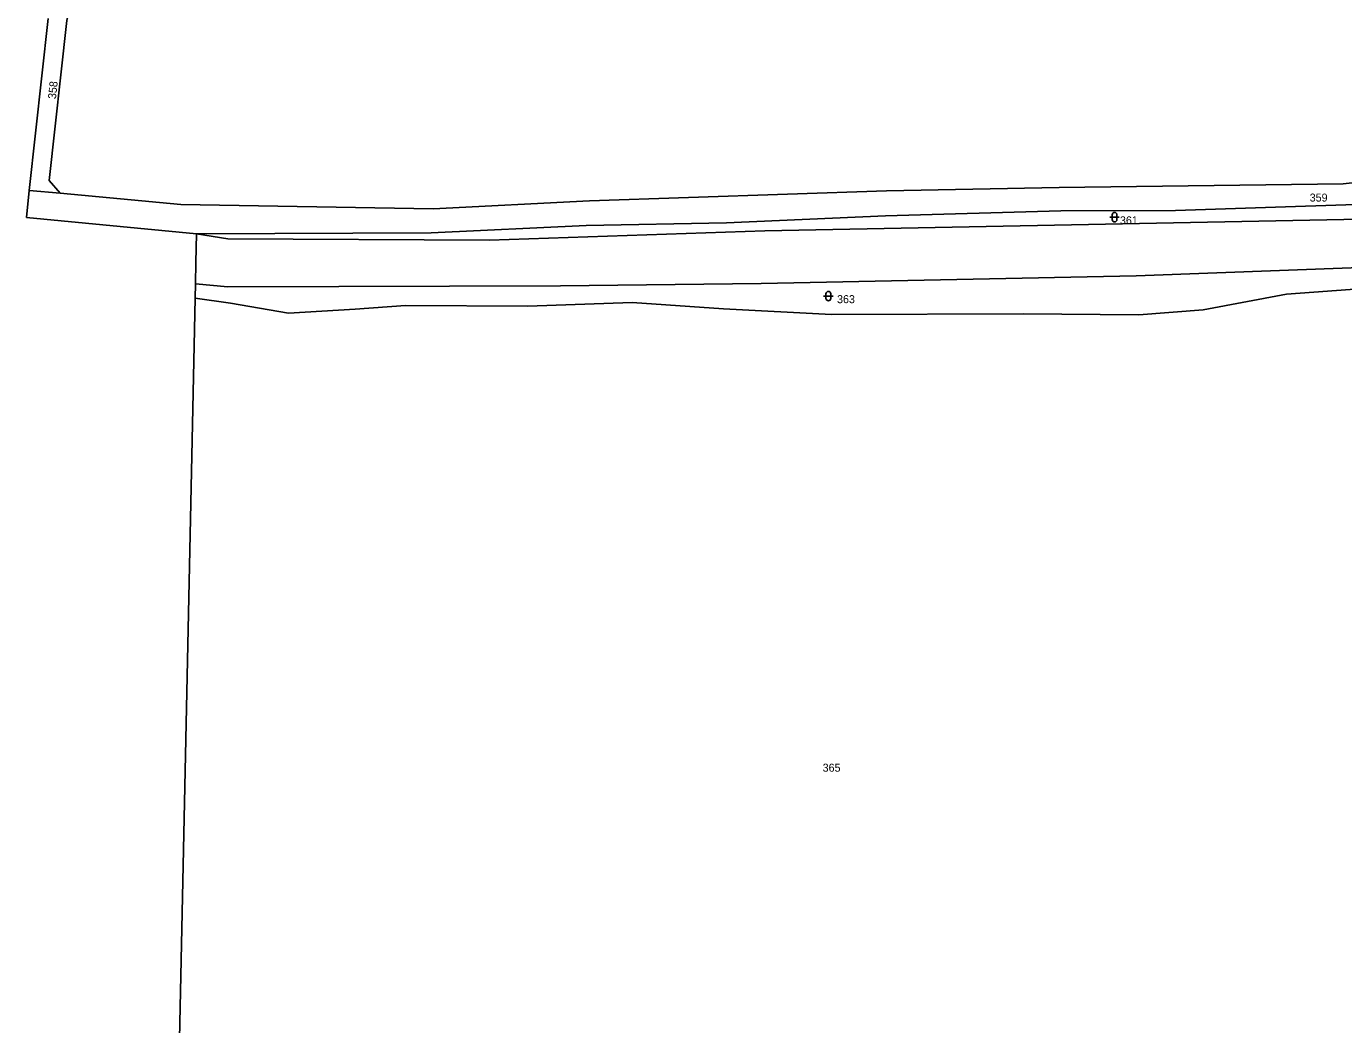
# Model space of a CAD drawing. Extents: x -769392 to -767038, y -1018329 to -1015269.
# Drawn here: x -769084.7 to -768805, y -1016297.6 to -1016085.5 of the extents above; entities that cross this region are included whole.
import ezdxf

# ---------------------------------------------------------------- set-up
doc = ezdxf.new("R2010")
doc.units = 0
doc.header["$LTSCALE"] = 0.68
doc.layers.add('1', color=7, linetype='Continuous', lineweight=25)
doc.layers.add('3', color=7, linetype='Continuous', lineweight=25)
doc.layers.add('2', color=7, linetype='Continuous')

msp = doc.modelspace()

# ---------------------------------------------------------------- linework, layer by layer
at = {"layer": '1'}
for p, q in [((-769080.14, -1016083.85), (-769084.11, -1016120.36)), ((-769084.11, -1016120.36), (-769084.74, -1016126.1)), ((-769084.11, -1016120.36), (-769077.57, -1016120.97)), ((-769084.74, -1016126.1), (-769048.63, -1016129.62)), ((-769048.85, -1016140.19), (-769048.91, -1016143.24)), ((-769048.91, -1016143.24), (-769052.49, -1016313.52))]:
    msp.add_line(p, q, dxfattribs=at)
for points in [[(-769072.33, -1016067.68), (-769076.16, -1016084.29), (-769079.86, -1016118.25), (-769077.57, -1016120.97)], [(-769077.57, -1016120.97), (-769051.96, -1016123.35), (-768998.31, -1016124.28), (-768965.15, -1016122.6), (-768902.06, -1016120.44), (-768865.37, -1016119.73), (-768805.12, -1016118.98), (-768769.94, -1016115), (-768749.97, -1016114.84), (-768736.74, -1016116.15), (-768689.9, -1016125.81), (-768656.93, -1016129.38), (-768637.88, -1016131.28), (-768596.9, -1016133.83)], [(-768594.7, -1016141.25), (-768631.63, -1016137.21), (-768650.19, -1016134.74), (-768717.39, -1016127.21), (-768738.73, -1016121.28), (-768749.98, -1016120.03), (-768769.94, -1016120.01), (-768778.71, -1016121.23), (-768783.28, -1016122.74), (-768840.7, -1016124.64), (-768865.08, -1016124.72), (-768902.28, -1016125.77), (-768936.05, -1016127.23), (-768965.85, -1016127.81), (-768998.75, -1016129.36), (-769048.63, -1016129.62)], [(-769048.63, -1016129.62), (-769041.93, -1016130.68), (-768986.37, -1016130.93), (-768927.89, -1016128.95), (-768776.02, -1016126.01), (-768730.41, -1016128.41), (-768682.51, -1016133.05), (-768638.7, -1016137.06), (-768594.18, -1016142.99)], [(-769048.63, -1016129.62), (-769048.76, -1016135.67), (-769048.85, -1016140.19)], [(-768801.46, -1016136.73), (-768849.03, -1016138.54), (-768928.72, -1016140.13), (-768971.29, -1016140.65), (-769041.94, -1016140.83), (-769048.85, -1016140.19)], [(-769048.91, -1016143.24), (-769041.35, -1016144.34), (-769029.07, -1016146.43), (-769014.89, -1016145.59), (-769004.2, -1016144.79), (-768978.27, -1016144.96), (-768956.11, -1016144.16), (-768936.7, -1016145.55), (-768913.76, -1016146.69), (-768873.01, -1016146.55), (-768848.49, -1016146.76), (-768834.83, -1016145.72), (-768817.1, -1016142.4), (-768800.7, -1016141.18)]]:
    msp.add_lwpolyline(points, dxfattribs=at)
at = {"layer": '3'}
for p, q in [((-768854.631, -1016126.051), (-768852.629, -1016126.051)), ((-768854.131, -1016125.551), (-768854.131, -1016126.552)), ((-768853.129, -1016126.552), (-768853.129, -1016125.551)), ((-768915.421, -1016142.801), (-768913.419, -1016142.801)), ((-768914.921, -1016142.301), (-768914.921, -1016143.302)), ((-768913.919, -1016143.302), (-768913.919, -1016142.301))]:
    msp.add_line(p, q, dxfattribs=at)
for centre, start, end in [((-768853.63, -1016125.5509), 0, 180), ((-768853.63, -1016126.5509), 180, 359.98789), ((-768914.42, -1016142.3009), 0, 180), ((-768914.42, -1016143.3009), 180, 359.98789)]:
    msp.add_arc(centre, 0.5, start, end, dxfattribs=at)

# ---------------------------------------------------------------- texts
at = {"layer": '2'}
msp.add_text('358', height=1.7, rotation=84, dxfattribs=at).set_placement((-769078.467, -1016101.024))
for s, p in [('359', (-768812.19, -1016122.735)), ('361', (-768852.49, -1016127.575)), ('363', (-768912.57, -1016144.315)), ('365', (-768915.63, -1016243.835))]:
    msp.add_text(s, height=1.7, dxfattribs=at).set_placement(p)

doc.saveas('drawing.dxf')
